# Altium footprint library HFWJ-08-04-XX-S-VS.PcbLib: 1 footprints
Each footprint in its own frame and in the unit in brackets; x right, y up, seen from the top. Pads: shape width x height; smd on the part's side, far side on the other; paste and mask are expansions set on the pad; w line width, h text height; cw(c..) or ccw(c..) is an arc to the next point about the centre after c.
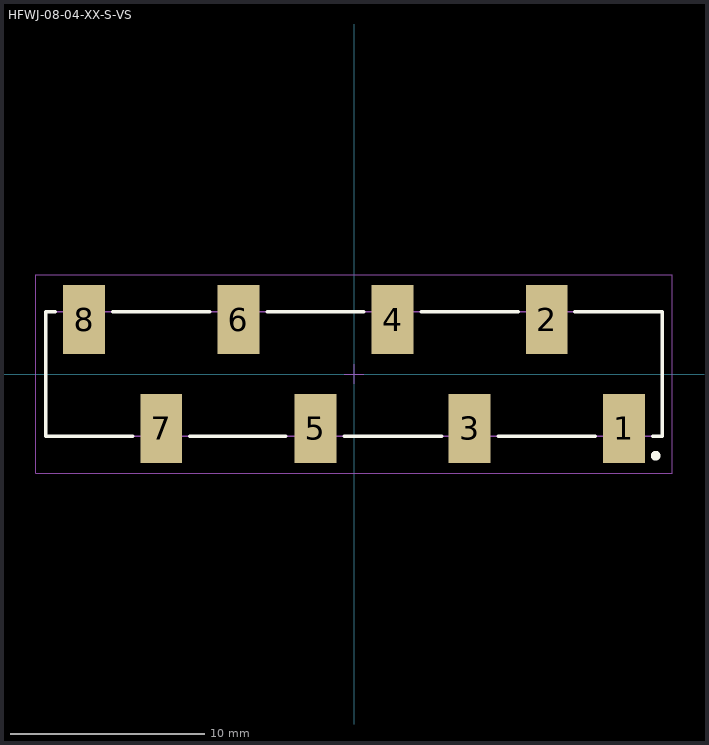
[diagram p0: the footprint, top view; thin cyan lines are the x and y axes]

## HFWJ-08-04-XX-S-VS [mm] "3.92mm pitch, 8 pin, high temp power terminal strip"
height 16.18
pads (8):
  rect 2.15x3.55 smd mask+0: 1(13.868,-2.794) 2(9.906,2.794) 3(5.944,-2.794) 4(1.981,2.794) 5(-1.981,-2.794) 6(-5.944,2.794) 7(-9.906,-2.794) 8(-13.868,2.794)
Top Overlay:
  circle w0.25: c15.5,-4.2 r0.125
  lines w0.178: -15.35,3.2 -15.85,3.2 -15.85,-3.2 -11.379,-3.2 ; -12.4,3.2 -7.4,3.2 ; -8.45,-3.2 -3.5,-3.2 ; -4.45,3.2 0.5,3.2 ; -0.5,-3.2 4.5,-3.2 ; 3.45,3.2 8.45,3.2 ; 7.4,-3.2 12.4,-3.2 ; 11.35,3.2 15.85,3.2 15.85,-3.2 15.35,-3.2
Mechanical 12:
  lines w0.001: -15.85,-3.2 -15.85,3.2 15.85,3.2 15.85,-3.2 -15.85,-3.2
Mechanical 13:
  lines w0.1: -15.85,-3.2 -15.85,3.2 15.85,3.2 15.85,-3.2 -15.85,-3.2
  text ".Designator" at 0,0 h1.52
Mechanical 15:
  lines w0.05: -0.5,0 0.5,0 ; 0,-0.5 0,0.5 ; -16.35,-5.1 -16.35,5.1 16.35,5.1 16.35,-5.1 -16.35,-5.1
